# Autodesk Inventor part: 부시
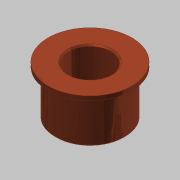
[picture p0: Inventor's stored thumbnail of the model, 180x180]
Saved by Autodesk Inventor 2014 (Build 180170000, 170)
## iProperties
Created: 2015-10
Part Number: 부시
Document SubType Name: Modeling
Designer: mdu
Density: 7.86 g/cm^3
Material: 강철, 연강
Mass: 246.97 g
Surface Area: 129.264 cm^2
Volume: 31.4212 cm^3
Appearance: 구리 - 새틴
Author: mdu
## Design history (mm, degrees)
sketch "스케치1"
  geometry: C1 r 31 at (0, 0) reference; C2 r 25 at (0, 0) reference; C3 r 30 at (0, 0) reference; 1 further point
  node "참조1"
  node "참조2"
  node "참조4"
extrude "돌출1" new body sketch "스케치1" distance "d0" = 3; taper "d1" = 0 deg
extrude "돌출2" join sketch "스케치1" distance "d2" = 35; taper "d3" = 0 deg
chamfer "모따기1" distance "d6" = 1; stored, may be unused: second distance "d7" = 2, angle "d8" = 45 deg
sketch "스케치3"
  geometry: C1 r 15 at (0, 0); 1 further point
  constraints: 1 centre point, 1 coincident
  dimensions: "d13" = 30 diameter of C1
extrude "돌출4" cut sketch "스케치3" stored distance "d14" = 10; taper "d15" = 0 deg
chamfer "모따기3" distance "d16" = 1; stored, may be unused: second distance "d17" = 2, angle "d18" = 45 deg
node "솔리드1"
